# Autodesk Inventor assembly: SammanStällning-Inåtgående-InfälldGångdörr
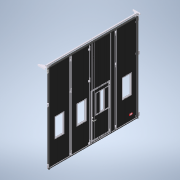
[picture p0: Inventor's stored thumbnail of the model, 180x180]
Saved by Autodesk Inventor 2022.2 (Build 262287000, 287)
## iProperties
Created: 2022-02
Part Number: SammanStällning-Inåtgående-InfälldGångdörr
Document SubType Name: Assembly
Designer: cl
Author: cl
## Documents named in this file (20)
- G:\AutoCad\Carl Lund\3D-modeller systemlösningar\3D-modell-systemlösning-2022\SammanStällning-Inåtgående-InfälldGångdörr.iam
- G:\AutoCad\Carl Lund\3D-modeller systemlösningar\3D-modell-systemlösning-2022\Parts\BladKomplett2022.iam
- G:\AutoCad\Carl Lund\3D-modeller systemlösningar\3D-modell-systemlösning-2022\Parts\MellanGångjärnH.ipt
- G:\AutoCad\Carl Lund\3D-modeller systemlösningar\3D-modell-systemlösning-2022\Parts\MellanGångjärnV.ipt
- G:\AutoCad\Carl Lund\3D-modeller systemlösningar\3D-modell-systemlösning-2022\Parts\Karmstyrning.ipt
- G:\AutoCad\Carl Lund\3D-modeller systemlösningar\3D-modell-systemlösning-2022\Parts\KarmgångjärnH.ipt
- G:\AutoCad\Carl Lund\3D-modeller systemlösningar\3D-modell-systemlösning-2022\Parts\KarmgångjärnV.ipt
- G:\AutoCad\Carl Lund\3D-modeller systemlösningar\3D-modell-systemlösning-2022\Parts\SidotätningUppe.ipt
- G:\AutoCad\Carl Lund\3D-modeller systemlösningar\3D-modell-systemlösning-2022\Parts\SidoTätning.ipt
- G:\AutoCad\Carl Lund\3D-modeller systemlösningar\3D-modell-systemlösning-2022\Parts\SläpList.ipt
- G:\AutoCad\Carl Lund\3D-modeller systemlösningar\3D-modell-systemlösning-2022\Parts\GummilistMellan.ipt
- G:\AutoCad\Carl Lund\3D-modeller systemlösningar\3D-modell-systemlösning-2022\Styrande.iam
- G:\AutoCad\Carl Lund\3D-modeller systemlösningar\3D-modell-systemlösning-2022\Parts\GarageregelHöger.ipt
- G:\AutoCad\Carl Lund\3D-modeller systemlösningar\3D-modell-systemlösning-2022\Parts\GarageregelVänster.ipt
- G:\AutoCad\Carl Lund\3D-modeller systemlösningar\3D-modell-systemlösning-2022\Parts\UppställningsbeslagHöger.ipt
- G:\AutoCad\Carl Lund\3D-modeller systemlösningar\3D-modell-systemlösning-2022\Parts\UppställningsbeslagVänster.ipt
- G:\AutoCad\Carl Lund\3D-modeller systemlösningar\3D-modell-systemlösning-2022\Parts\styrrulle.ipt
- G:\AutoCad\Carl Lund\3D-modeller systemlösningar\3D-modell-systemlösning-2022\Parts\Styrskena.ipt
- G:\AutoCad\Carl Lund\3D-modeller systemlösningar\3D-modell-systemlösning-2022\Parts\BladKomplettInfälld2022.iam
- G:\AutoCad\Carl Lund\3D-modeller systemlösningar\3D-modell-systemlösning-2022\Parts\Logga.ipt
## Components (50 placed, 18 different names)
1. BladKomplett2022:1 [sub-assembly] — Mate:1, Mate:2, Flush:1, Flush:2, Flush:3, Flush:8, Flush:28, Flush:29, Mate:28, Flush:30, Mate:42, Flush:73, Mate:39, Mate:43, Mate:47, Mate:48, Flush:99, Flush:100, Flush:101, Flush:102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
2. BladKomplett2022:2 [sub-assembly] — Flush:2, Flush:3, Flush:8, Flush:106, Mate:52, Flush:107, Flush:118, Flush:121, Mate:65, Flush:148, Flush:149, Mate:82, Flush:170, Flush:171, Flush:177
3. BladKomplett2022:3 [sub-assembly] — Flush:30, Flush:101, Flush:102, Mate:53, Flush:114, Flush:115
4. BladKomplett2022:4 [sub-assembly] — Flush:32, Flush:100, Flush:103, Mate:54, Flush:122, Flush:123, Flush:128, Mate:64, Flush:146, Flush:147
5. BladKomplett2022:5 [sub-assembly] — Flush:31, Flush:99, Flush:104, Flush:129, Mate:55, Flush:130, Mate:63, Flush:144, Flush:145, Mate:81, Flush:168, Flush:169
6. Logga:1 — Mate:181, Mate:182, Mate:183
7. BladKomplett2022:6 [sub-assembly] — Mate:28, Flush:28, Flush:29, Flush:31, Flush:32, Mate:38, Flush:74, Mate:49, Mate:50, Flush:131, Flush:134, Flush:137, Mate:56, Flush:138, Flush:139, Mate:58, Mate:59, Mate:62, Flush:142, Flush:143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
8. BladKomplettInfälld2022:1 [sub-assembly] — Flush:176, Flush:177, Flush:178, Mate:177, Flush:179, Flush:180, Flush:181, Mate:178, Flush:187, Flush:188, Flush:189, Mate:180, Flush:190
9. GarageregelHöger:1 — Flush:156, Flush:157, Flush:158
10. GarageregelHöger:2 — Mate:77, Flush:154, Flush:155, Flush:156, Flush:157, Flush:158
11. GarageregelVänster:1 — Flush:161, Flush:162, Flush:163
12. GarageregelVänster:2 — Mate:78, Flush:159, Flush:160, Flush:161, Flush:162, Flush:163
13. Karmstyrning:2 — Mate:38, Mate:56, Flush:138, Flush:141
14. Karmstyrning:3 — Mate:39, Mate:43, Flush:140
15. Karmstyrning:4 — Mate:42, Mate:60, Mate:61, Flush:141
16. KarmgångjärnH:1 — Flush:74, Mate:49, Mate:50, Flush:166, Flush:167, Mate:80
17. KarmgångjärnV:1 — Flush:73, Mate:47, Mate:48, Flush:164, Flush:165, Mate:79
18. Karmstyrning:1 — Flush:139, Mate:58, Mate:59, Flush:140
19. MellanGångjärnV:3 — Flush:110, Flush:111, Flush:113
20. MellanGångjärnV:2 — Flush:108, Flush:109, Flush:110, Flush:111, Flush:112
21. MellanGångjärnV:1 — Flush:106, Mate:52, Flush:107, Flush:108, Flush:109
22. MellanGångjärnH:2 — Flush:116, Flush:117, Flush:118, Flush:119, Flush:120
23. MellanGångjärnH:3 — Flush:119, Flush:120, Flush:121
24. MellanGångjärnH:1 — Mate:53, Flush:114, Flush:115, Flush:116, Flush:117
25. MellanGångjärnV:6 — Flush:124, Flush:125, Flush:126, Flush:127, Flush:128
26. MellanGångjärnV:5 — Flush:126, Flush:127, Flush:129
27. MellanGångjärnV:4 — Mate:54, Flush:122, Flush:123, Flush:124, Flush:125
28. MellanGångjärnH:5 — Flush:132, Flush:133, Flush:134
29. MellanGångjärnH:6 — Flush:135, Flush:136, Flush:137
30. MellanGångjärnH:4 — Mate:55, Flush:130, Flush:131, Flush:132, Flush:133, Flush:135, Flush:136
31. MellanGångjärnV:7 — Flush:181, Mate:178, Flush:182, Flush:183, Flush:184, Flush:185, Flush:186
32. MellanGångjärnV:8 — Flush:183, Flush:184, Flush:187
33. MellanGångjärnV:9 — Flush:185, Flush:186, Flush:188
34. GummilistMellan:6 — Mate:177, Flush:179, Flush:180
35. GummilistMellan:2 — Mate:63, Flush:144, Flush:145
36. GummilistMellan:3 — Mate:64, Flush:146, Flush:147
37. GummilistMellan:4 — Mate:65, Flush:148, Flush:149
38. GummilistMellan:5 — Mate:66, Flush:150, Flush:151
39. SidotätningUppe:1 — Mate:67, Mate:68, Flush:152, Mate:71, Mate:74
40. SidoTätning:1 — Mate:69, Mate:70, Mate:71, Mate:76
41. SidoTätning:2 — Mate:72, Mate:73, Mate:74
42. SläpList:1 — Mate:75, Flush:153, Mate:76
43. GummilistMellan:1 — Mate:62, Flush:142, Flush:143
44. styrrulle:3 — Flush:189, Mate:180, Flush:190
45. UppställningsbeslagVänster:1 — Flush:166, Flush:167, Mate:80
46. styrrulle:1 — Mate:81, Flush:168, Flush:169
47. styrrulle:2 — Mate:82, Flush:170, Flush:171
48. Styrskena:1 — Mate:83, Flush:172, Flush:174, Mate:176, Flush:175, Mate:179
49. Styrskena:2 — Flush:174, Mate:176, Flush:175
50. UppställningsbeslagHöger:1 — Flush:164, Flush:165, Mate:79, Mate:83, Flush:172, Mate:179
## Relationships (151: Flush 101, Mate 50)
- Mate:1: BladKomplett2022:1
- Mate:2: BladKomplett2022:1
- Flush:1: BladKomplett2022:1
- Flush:2: BladKomplett2022:1 ↔ BladKomplett2022:2
- Flush:3: BladKomplett2022:1 ↔ BladKomplett2022:2
- Flush:8: BladKomplett2022:1 ↔ BladKomplett2022:2
- Mate:28: BladKomplett2022:1 ↔ BladKomplett2022:6
- Flush:28: BladKomplett2022:1 ↔ BladKomplett2022:6
- Flush:29: BladKomplett2022:1 ↔ BladKomplett2022:6
- Flush:30: BladKomplett2022:1 ↔ BladKomplett2022:3
- Flush:31: BladKomplett2022:5 ↔ BladKomplett2022:6
- Flush:32: BladKomplett2022:4 ↔ BladKomplett2022:6
- Mate:38: BladKomplett2022:6 ↔ Karmstyrning:2
- Mate:39: BladKomplett2022:1 ↔ Karmstyrning:3
- Mate:42: BladKomplett2022:1 ↔ Karmstyrning:4
- Mate:43: BladKomplett2022:1 ↔ Karmstyrning:3
- Flush:73: BladKomplett2022:1 ↔ KarmgångjärnV:1
- Mate:47: BladKomplett2022:1 ↔ KarmgångjärnV:1
- Mate:48: BladKomplett2022:1 ↔ KarmgångjärnV:1
- Flush:74: BladKomplett2022:6 ↔ KarmgångjärnH:1
- Mate:49: BladKomplett2022:6 ↔ KarmgångjärnH:1
- Mate:50: BladKomplett2022:6 ↔ KarmgångjärnH:1
- Flush:99: BladKomplett2022:1 ↔ BladKomplett2022:5
- Flush:100: BladKomplett2022:1 ↔ BladKomplett2022:4
- Flush:101: BladKomplett2022:1 ↔ BladKomplett2022:3
- Flush:102: BladKomplett2022:1 ↔ BladKomplett2022:3
- Flush:103: BladKomplett2022:1 ↔ BladKomplett2022:4
- Flush:104: BladKomplett2022:1 ↔ BladKomplett2022:5
- Flush:106: BladKomplett2022:2 ↔ MellanGångjärnV:1
- Mate:52: BladKomplett2022:2 ↔ MellanGångjärnV:1
- Flush:107: BladKomplett2022:2 ↔ MellanGångjärnV:1
- Flush:108: MellanGångjärnV:2 ↔ MellanGångjärnV:1
- Flush:109: MellanGångjärnV:2 ↔ MellanGångjärnV:1
- Flush:110: MellanGångjärnV:3 ↔ MellanGångjärnV:2
- Flush:111: MellanGångjärnV:3 ↔ MellanGångjärnV:2
- Flush:112: BladKomplett2022:1 ↔ MellanGångjärnV:2
- Flush:113: BladKomplett2022:1 ↔ MellanGångjärnV:3
- Mate:53: BladKomplett2022:3 ↔ MellanGångjärnH:1
- Flush:114: BladKomplett2022:3 ↔ MellanGångjärnH:1
- Flush:115: BladKomplett2022:3 ↔ MellanGångjärnH:1
- Flush:116: MellanGångjärnH:2 ↔ MellanGångjärnH:1
- Flush:117: MellanGångjärnH:2 ↔ MellanGångjärnH:1
- Flush:118: BladKomplett2022:2 ↔ MellanGångjärnH:2
- Flush:119: MellanGångjärnH:2 ↔ MellanGångjärnH:3
- Flush:120: MellanGångjärnH:2 ↔ MellanGångjärnH:3
- Flush:121: BladKomplett2022:2 ↔ MellanGångjärnH:3
- Mate:54: BladKomplett2022:4 ↔ MellanGångjärnV:4
- Flush:122: BladKomplett2022:4 ↔ MellanGångjärnV:4
- Flush:123: BladKomplett2022:4 ↔ MellanGångjärnV:4
- Flush:124: MellanGångjärnV:6 ↔ MellanGångjärnV:4
- Flush:125: MellanGångjärnV:6 ↔ MellanGångjärnV:4
- Flush:126: MellanGångjärnV:6 ↔ MellanGångjärnV:5
- Flush:127: MellanGångjärnV:6 ↔ MellanGångjärnV:5
- Flush:128: BladKomplett2022:4 ↔ MellanGångjärnV:6
- Flush:129: BladKomplett2022:5 ↔ MellanGångjärnV:5
- Mate:55: BladKomplett2022:5 ↔ MellanGångjärnH:4
- Flush:130: BladKomplett2022:5 ↔ MellanGångjärnH:4
- Flush:131: BladKomplett2022:6 ↔ MellanGångjärnH:4
- Flush:132: MellanGångjärnH:5 ↔ MellanGångjärnH:4
- Flush:133: MellanGångjärnH:5 ↔ MellanGångjärnH:4
- Flush:134: BladKomplett2022:6 ↔ MellanGångjärnH:5
- Flush:135: MellanGångjärnH:6 ↔ MellanGångjärnH:4
- Flush:136: MellanGångjärnH:6 ↔ MellanGångjärnH:4
- Flush:137: BladKomplett2022:6 ↔ MellanGångjärnH:6
- Mate:56: BladKomplett2022:6 ↔ Karmstyrning:2
- Flush:138: BladKomplett2022:6 ↔ Karmstyrning:2
- Flush:139: BladKomplett2022:6 ↔ Karmstyrning:1
- Mate:58: BladKomplett2022:6 ↔ Karmstyrning:1
- Mate:59: BladKomplett2022:6 ↔ Karmstyrning:1
- Flush:140: Karmstyrning:3 ↔ Karmstyrning:1
- Mate:60: BladKomplett2022:1 ↔ Karmstyrning:4
- Mate:61: BladKomplett2022:1 ↔ Karmstyrning:4
- Flush:141: Karmstyrning:2 ↔ Karmstyrning:4
- Mate:62: BladKomplett2022:6 ↔ GummilistMellan:1
- Flush:142: BladKomplett2022:6 ↔ GummilistMellan:1
- Flush:143: BladKomplett2022:6 ↔ GummilistMellan:1
- Mate:63: BladKomplett2022:5 ↔ GummilistMellan:2
- Flush:144: BladKomplett2022:5 ↔ GummilistMellan:2
- Flush:145: BladKomplett2022:5 ↔ GummilistMellan:2
- Mate:64: BladKomplett2022:4 ↔ GummilistMellan:3
- Flush:146: BladKomplett2022:4 ↔ GummilistMellan:3
- Flush:147: BladKomplett2022:4 ↔ GummilistMellan:3
- Mate:65: BladKomplett2022:2 ↔ GummilistMellan:4
- Flush:148: BladKomplett2022:2 ↔ GummilistMellan:4
- Flush:149: BladKomplett2022:2 ↔ GummilistMellan:4
- Mate:66: BladKomplett2022:1 ↔ GummilistMellan:5
- Flush:150: BladKomplett2022:1 ↔ GummilistMellan:5
- Flush:151: BladKomplett2022:1 ↔ GummilistMellan:5
- Mate:67: BladKomplett2022:1 ↔ SidotätningUppe:1
- Mate:68: BladKomplett2022:1 ↔ SidotätningUppe:1
- Flush:152: BladKomplett2022:6 ↔ SidotätningUppe:1
- Mate:69: BladKomplett2022:6 ↔ SidoTätning:1
- Mate:70: BladKomplett2022:6 ↔ SidoTätning:1
- Mate:71: SidotätningUppe:1 ↔ SidoTätning:1
- Mate:72: BladKomplett2022:1 ↔ SidoTätning:2
- Mate:73: BladKomplett2022:1 ↔ SidoTätning:2
- Mate:74: SidotätningUppe:1 ↔ SidoTätning:2
- Mate:75: BladKomplett2022:1 ↔ SläpList:1
- Flush:153: BladKomplett2022:1 ↔ SläpList:1
- Mate:76: SidoTätning:1 ↔ SläpList:1
- Mate:77: BladKomplett2022:1 ↔ GarageregelHöger:2
- Flush:154: BladKomplett2022:1 ↔ GarageregelHöger:2
- Flush:155: BladKomplett2022:1 ↔ GarageregelHöger:2
- Flush:156: GarageregelHöger:1 ↔ GarageregelHöger:2
- Flush:157: GarageregelHöger:1 ↔ GarageregelHöger:2
- Flush:158: GarageregelHöger:1 ↔ GarageregelHöger:2
- Mate:78: BladKomplett2022:6 ↔ GarageregelVänster:2
- Flush:159: BladKomplett2022:6 ↔ GarageregelVänster:2
- Flush:160: BladKomplett2022:6 ↔ GarageregelVänster:2
- Flush:161: GarageregelVänster:1 ↔ GarageregelVänster:2
- Flush:162: GarageregelVänster:1 ↔ GarageregelVänster:2
- Flush:163: GarageregelVänster:1 ↔ GarageregelVänster:2
- Flush:164: KarmgångjärnV:1 ↔ UppställningsbeslagHöger:1
- Flush:165: KarmgångjärnV:1 ↔ UppställningsbeslagHöger:1
- Mate:79: KarmgångjärnV:1 ↔ UppställningsbeslagHöger:1
- Flush:166: KarmgångjärnH:1 ↔ UppställningsbeslagVänster:1
- Flush:167: KarmgångjärnH:1 ↔ UppställningsbeslagVänster:1
- Mate:80: KarmgångjärnH:1 ↔ UppställningsbeslagVänster:1
- Mate:81: BladKomplett2022:5 ↔ styrrulle:1
- Flush:168: BladKomplett2022:5 ↔ styrrulle:1
- Flush:169: BladKomplett2022:5 ↔ styrrulle:1
- Mate:82: BladKomplett2022:2 ↔ styrrulle:2
- Flush:170: BladKomplett2022:2 ↔ styrrulle:2
- Flush:171: BladKomplett2022:2 ↔ styrrulle:2
- Mate:83: Styrskena:1 ↔ UppställningsbeslagHöger:1
- Flush:172: Styrskena:1 ↔ UppställningsbeslagHöger:1
- Flush:174: Styrskena:1 ↔ Styrskena:2
- Mate:176: Styrskena:1 ↔ Styrskena:2
- Flush:175: Styrskena:1 ↔ Styrskena:2
- Flush:176: BladKomplett2022:1 ↔ BladKomplettInfälld2022:1
- Flush:177: BladKomplett2022:2 ↔ BladKomplettInfälld2022:1
- Flush:178: BladKomplett2022:1 ↔ BladKomplettInfälld2022:1
- Mate:177: BladKomplettInfälld2022:1 ↔ GummilistMellan:6
- Flush:179: BladKomplettInfälld2022:1 ↔ GummilistMellan:6
- Flush:180: BladKomplettInfälld2022:1 ↔ GummilistMellan:6
- Flush:181: BladKomplettInfälld2022:1 ↔ MellanGångjärnV:7
- Mate:178: BladKomplettInfälld2022:1 ↔ MellanGångjärnV:7
- Flush:182: BladKomplett2022:1 ↔ MellanGångjärnV:7
- Flush:183: MellanGångjärnV:7 ↔ MellanGångjärnV:8
- Flush:184: MellanGångjärnV:7 ↔ MellanGångjärnV:8
- Flush:185: MellanGångjärnV:7 ↔ MellanGångjärnV:9
- Flush:186: MellanGångjärnV:7 ↔ MellanGångjärnV:9
- Flush:187: BladKomplettInfälld2022:1 ↔ MellanGångjärnV:8
- Flush:188: BladKomplettInfälld2022:1 ↔ MellanGångjärnV:9
- Mate:179: Styrskena:1 ↔ UppställningsbeslagHöger:1
- Flush:189: BladKomplettInfälld2022:1 ↔ styrrulle:3
- Mate:180: BladKomplettInfälld2022:1 ↔ styrrulle:3
- Flush:190: BladKomplettInfälld2022:1 ↔ styrrulle:3
- Mate:181: Logga:1 ↔ BladKomplett2022:6
- Mate:182: Logga:1 ↔ BladKomplett2022:6
- Mate:183: Logga:1 ↔ BladKomplett2022:6
## Named parameters: Blad2 = 1012.5 mm, Blad3 = 0, Blad4 = 0, Blad5 = 1012.5 mm, MGJ12Djup = 0, MGJ12Bredd = 0, MGJ56Djup = 0, MGJ56Bredd = 0, MGJ23Djup = 48 mm, MGJ45Djup = 48 mm, GarageRegel5 = 0, GarageRegel6 = 0, BladBredd = 987.5 mm, Fönsterhöjd = 862 mm, Blad2_1 = 1012.5 mm, Blad3_1 = 0, Blad4_1 = 0, Blad5_1 = 1012.5 mm, Blad6 = 2025 mm, MGJ12Djup_1 = 0, MGJ12Bredd_1 = 0, MGJ2Djup = 0, MGJ2Bredd = 5012.5 mm, MGJ56Djup_1 = 0, MGJ56Bredd_1 = 0, MGJ23Djup_1 = 48 mm, MGJ45Djup_1 = 48 mm, GarageRegel5_1 = 0, GarageRegel6_1 = 0, Styrrulle2Djup = 0, FönsterhöjdStyrning = 862 mm, FönsterKarm = 54 mm, AndraGlasraden = 0, BrösthöjdStyrning2 = 0.0001 mm, InfälldGångDörr = 0, Infälldstyr = 845.83333 mm
